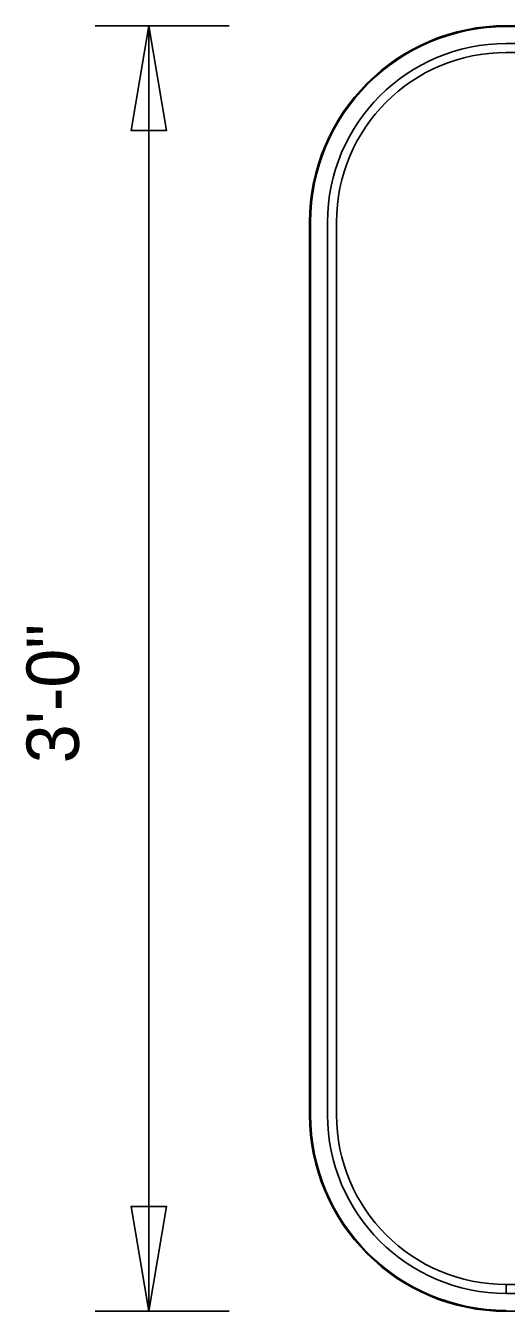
# Model space of a CAD drawing. Extents: x 0 to 770, y 0 to 495.
# Drawn here: x 394.6 to 426.7, y 213.2 to 299.1 of the extents above; entities that cross this region are included whole.
import ezdxf

# ---------------------------------------------------------------- set-up
doc = ezdxf.new("R2010")
doc.units = 0
for name, color, linetype in [('Dimension', 7, 'Continuous'), ('GSBWFill', 7, 'Continuous'), ('GSColorFill', 7, 'Continuous'), ('GSDims', 7, 'Continuous'), ('GSOutline', 7, 'Continuous'), ('TextStructures', 7, 'Continuous')]:
    doc.layers.add(name, color=color, linetype=linetype)

msp = doc.modelspace()

# ---------------------------------------------------------------- linework, layer by layer
at = {"layer": 'Dimension'}
for points in [[(402.809, 299.122), (401.621, 292.106), (403.998, 292.106)], [(402.809, 213.155), (403.998, 220.172), (401.621, 220.172)]]:
    msp.add_lwpolyline(points, close=True, dxfattribs=at)
at = {"layer": 'GSBWFill'}
for p, q in [((529.372, 299.122), (426.689, 299.122)), ((529.372, 297.928), (426.689, 297.928)), ((426.689, 297.331), (529.372, 297.331)), ((413.555, 285.988), (413.555, 226.289)), ((414.749, 285.988), (414.749, 226.289)), ((415.346, 226.289), (415.346, 285.988)), ((426.689, 214.349), (426.689, 214.946)), ((426.689, 213.155), (529.372, 213.155))]:
    msp.add_line(p, q, dxfattribs=at)
for centre, radius, start, end in [((426.689, 285.988), 13.134, 90, 180), ((426.689, 285.988), 11.94, 90, 180), ((426.689, 285.988), 11.343, 90, 180), ((426.689, 226.289), 13.134, 180, 270), ((426.689, 226.289), 11.94, 180, 270), ((426.689, 226.289), 11.343, 180, 270)]:
    msp.add_arc(centre, radius, start, end, dxfattribs=at)
at = {"layer": 'GSColorFill'}
for p, q in [((529.372, 299.122), (426.689, 299.122)), ((529.372, 299.122), (426.689, 299.122)), ((426.689, 299.063), (529.372, 299.063)), ((529.372, 297.928), (426.689, 297.928)), ((426.689, 297.331), (529.372, 297.331)), ((413.555, 285.988), (413.555, 226.289)), ((413.555, 285.988), (413.555, 226.289)), ((413.615, 226.289), (413.615, 285.988)), ((414.749, 285.988), (414.749, 226.289)), ((415.346, 226.289), (415.346, 285.988)), ((426.689, 214.349), (426.689, 214.946)), ((426.689, 213.155), (426.689, 213.215)), ((426.689, 213.155), (529.372, 213.155))]:
    msp.add_line(p, q, dxfattribs=at)
for centre, radius, start, end in [((426.689, 285.988), 13.134, 90, 180), ((426.689, 285.988), 13.134, 90, 180), ((426.689, 285.988), 13.074, 90, 180), ((426.689, 285.988), 11.94, 90, 180), ((426.689, 285.988), 11.343, 90, 180), ((426.689, 226.289), 13.134, 180, 270), ((426.689, 226.289), 13.134, 180, 270), ((426.689, 226.289), 13.074, 180, 270), ((426.689, 226.289), 11.94, 180, 270), ((426.689, 226.289), 11.343, 180, 270)]:
    msp.add_arc(centre, radius, start, end, dxfattribs=at)
at = {"layer": 'GSDims'}
for p, q in [((408.182, 299.122), (399.227, 299.122)), ((402.809, 213.155), (402.809, 299.122)), ((408.182, 213.155), (399.227, 213.155))]:
    msp.add_line(p, q, dxfattribs=at)
at = {"layer": 'GSOutline'}
for p, q in [((529.372, 299.122), (426.689, 299.122)), ((529.372, 297.928), (426.689, 297.928)), ((529.372, 297.331), (426.689, 297.331)), ((413.555, 285.988), (413.555, 226.289)), ((414.749, 285.988), (414.749, 226.289)), ((415.346, 285.988), (415.346, 226.289)), ((426.689, 214.946), (529.372, 214.946)), ((426.689, 214.349), (529.372, 214.349)), ((426.689, 213.155), (529.372, 213.155))]:
    msp.add_line(p, q, dxfattribs=at)
for centre, radius, start, end in [((426.689, 285.988), 13.134, 90, 180), ((426.689, 285.988), 11.94, 90, 180), ((426.689, 285.988), 11.343, 90, 180), ((426.689, 226.289), 13.134, 180, 270), ((426.689, 226.289), 11.94, 180, 270), ((426.689, 226.289), 11.343, 180, 270)]:
    msp.add_arc(centre, radius, start, end, dxfattribs=at)

# ---------------------------------------------------------------- texts
at = {"layer": 'TextStructures'}
msp.add_text('3\'-0"', height=3.5, rotation=90, dxfattribs=at).set_placement((398.141, 249.803))

doc.saveas('drawing.dxf')
